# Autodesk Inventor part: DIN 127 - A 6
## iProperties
Comments: To add or edit properties for Autodesk Inventor files, use iProperties.
Created: 2004-02
Part Number: DIN 127 - A 6
Vendor: Autodesk Inc.
Document SubType Name: Modeling
Designer: Administrator
Material: A4
Description: Federring
Standard: DIN 127
Manufacturer: Standard
Standards Organization: Custom
Alert: To add or edit properties for Autodesk Inventor files, use iProperties.
Control State: 0
Master: False
Checked Out: False
Shininess: 64.0
Length Units: 11269
Angle Units: 11279
Time Units: 11290
Mass Units: 11283
Length Display Precision: 3
Angle Display Precision: 2
Compacted: True
Classification: un/spsc 31161811
ArtNr: L30020
Farbe: Metal-Steel
Zuschnitt: 2mm
GesGewicht: 0,0kg
Zeichnungsnummer: DIN 127 - A 6
Density: 0.0
Volumn: 0.0
Area: 0.0
PropertySet Name: Model Information
Author: Administrator
Revision Number: 5
Title: Federing für M6
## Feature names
1. Körper [Extrusion]
2. Schnitt [Extrusion]
